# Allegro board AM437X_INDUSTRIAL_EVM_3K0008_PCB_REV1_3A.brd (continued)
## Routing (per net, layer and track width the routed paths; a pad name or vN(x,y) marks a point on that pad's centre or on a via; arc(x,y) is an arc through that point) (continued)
DDR_A6: length 94.3
  TOP w0.102: v1(81.34,60.82) 81.51,60.82 81.78,61.11 U11.R4 ; U20.R8 76.46,29.62 v1(76.46,29.62) 77.05,29.62 77.25,29.82 77.49,29.82 77.49,29.82 78.12,29.82 80.84,32.54 80.84,33.94 81.36,34.46 81.36,46.05 81.24,46.17 79.67,46.17 79.55,46.29 79.55,46.46 79.67,46.58 81.24,46.58 81.36,46.7 81.36,46.87 81.24,46.98 79.67,46.98 79.55,47.1 79.55,47.27 79.67,47.39 81.24,47.39 81.36,47.51 81.36,47.9 81.24,48.01 80.56,48.01 80.44,48.13 80.44,48.3 80.56,48.42 81.24,48.42 81.36,48.54 81.36,48.99 v1(81.18,49.17) ; U21.R8 v1(95.13,29.62)
  L3_SIG1 w0.102: v1(95.13,29.62) 94.75,30 93.2,30 92.79,29.59 92.21,29.59 92.18,29.62 91.84,29.62 90.45,28.23 90.45,26.15 90.27,25.97 88.51,25.97 87.03,27.46 86.01,27.46 85.89,27.34 85.89,26.96 85.77,26.84 85.6,26.84 85.48,26.96 85.48,27.34 85.36,27.46 85.2,27.46 85.08,27.34 85.08,26.96 84.96,26.84 84.79,26.84 84.67,26.96 84.67,27.34 84.55,27.46 84.38,27.46 84.26,27.34 84.26,26.96 84.14,26.84 83.98,26.84 83.86,26.96 83.86,27.34 83.74,27.46 83.57,27.46 83.45,27.34 83.45,26.96 83.33,26.84 83.16,26.84 83.04,26.96 83.04,27.34 82.93,27.46 82.76,27.46 82.64,27.34 82.64,27.06 82.52,26.94 82.35,26.94 82.23,27.06 82.23,27.34 82.11,27.46 81.94,27.46 81.83,27.34 81.83,27.06 81.71,26.94 81.54,26.94 81.42,27.06 81.42,27.34 81.3,27.46 81.13,27.46 81.01,27.34 81.01,27.06 80.89,26.94 80.73,26.94 80.61,27.06 80.61,27.34 80.49,27.46 80.32,27.46 80.2,27.34 80.2,27.06 80.08,26.94 79.91,26.94 79.79,27.06 79.79,27.34 79.67,27.46 78.62,27.46 78.5,27.58 78.5,27.69 78.38,27.81 78.22,27.81 78.1,27.69 78.1,27.58 77.98,27.46 77.42,27.46 77.05,27.83 77.05,28.8 76.46,29.38 v1(76.46,29.62)
  L4_SIG2 w0.102: v1(81.34,60.82) 81.34,60.21 80.97,59.84 80.97,59.25 80.85,59.13 80.37,59.13 80.25,59.01 80.25,58.84 80.37,58.72 80.85,58.72 80.97,58.6 80.97,57.21 81.31,56.87 81.31,56.4 81.08,56.16 81.08,55.97 80.96,55.85 79.91,55.85 79.79,55.73 79.79,55.56 79.91,55.45 80.96,55.45 81.08,55.33 81.08,55.16 80.96,55.04 79.91,55.04 79.79,54.92 79.79,54.75 79.91,54.63 80.96,54.63 81.08,54.51 81.08,53.82 81.31,53.59 81.89,53.59 82.06,53.42 82.06,51.9 81.94,51.78 81.86,51.78 81.74,51.66 81.74,51.49 81.86,51.37 81.94,51.37 82.06,51.25 82.06,51.09 81.94,50.97 80.92,50.97 80.8,50.85 80.8,50.68 80.92,50.56 81.94,50.56 82.06,50.44 82.06,50.08 81.94,49.96 81.79,49.96 81.67,49.84 81.67,49.68 81.79,49.56 81.94,49.56 82.06,49.44 82.06,49.27 81.94,49.15 81.79,49.15 81.67,49.03 81.67,48.86 81.79,48.74 81.94,48.74 82.06,48.62 82.06,48.39 81.68,48.01 81.1,48.01 80.9,48.21 80.9,48.89 v1(81.18,49.17)
  BOTTOM w0.102: v1(95.13,29.62) 96.11,29.62 96.64,29.08 R516.2
DDR_A7: length 89.3
  TOP w0.102: U21.R2 89.93,29.23 v1(89.56,29.61) ; v1(80.92,60.43) 80.95,60.4 81.54,60.4 U11.R3 ; v1(71.66,29.57) 71.31,29.22 U20.R2 71.65,28.83 72.64,28.83 72.97,28.51 72.97,27.96 72.68,27.67 72.68,26.93 74.09,25.52 79.75,25.52 85.65,31.42 85.65,34.97 85.27,35.36 85.27,43.31 v1(85.44,43.48)
  L4_SIG2 w0.102: v1(85.44,43.48) 83.08,43.48 82.96,43.6 82.96,43.95 82.83,44.08 82.66,44.08 82.55,43.97 82.55,43.6 82.43,43.48 82.26,43.48 82.14,43.6 82.14,44.09 82.02,44.21 81.86,44.21 81.74,44.09 81.74,43.6 81.62,43.48 81.3,43.48 81,43.78 81,46.17 80.34,46.83 80.34,51.94 79.24,53.05 79.24,56.37 80.24,57.37 80.24,57.71 79.95,58.01 79.95,59.46 v1(80.92,60.43) ; v1(89.56,29.61) 89.03,29.08 89.03,27.67 88.7,27.34 88,27.34 87.61,27.73 87.44,27.73 87.2,27.49 87.03,27.49 86.91,27.61 86.91,27.78 87.15,28.02 87.15,28.19 87.03,28.31 86.86,28.31 86.62,28.07 86.45,28.07 86.33,28.19 86.33,28.36 86.58,28.6 86.58,28.77 86.46,28.88 86.29,28.88 86.05,28.64 85.88,28.64 85.76,28.76 85.76,28.93 86,29.17 86,29.34 85.8,29.54 78.66,29.54 78.05,28.92 77.19,28.92 76.87,29.24 76.87,29.84 76.41,30.3 76.41,30.56 76.08,30.89 75.59,30.89 75.25,30.55 75.25,30.25 74.99,29.99 74.54,29.99 74.12,29.57 72.97,29.57 72.87,29.66 72.4,29.66 72.3,29.57 v1(71.66,29.57)
  BOTTOM w0.102: R534.2 87.76,27.38 88.12,27.75 88.12,28.38 88.45,28.7 88.6,28.7 89.5,29.61 v1(89.56,29.61)
DDR_A8: length 97.2
  TOP w0.102: U20.T8 76.06,28.5 v1(76.39,28.83) 77.24,28.83 77.28,28.87 77.79,28.87 78.79,29.87 78.81,29.87 79.58,30.65 79.58,30.67 81.27,32.36 81.27,33.8 81.77,34.3 81.77,47.46 v1(82.21,47.9) ; v1(81.79,57.73) 82.19,58.14 82.19,58.98 82.09,59.08 82.09,59.48 81.78,59.78 U11.R2 ; v1(95.17,28.78) U21.T8 94.73,28.04 95.76,27.01 R221.2
  L3_SIG1 w0.102: v1(95.17,28.78) 94.35,28.78 93.52,29.62 93.12,29.62 92.88,29.39 92.88,29.31 91.47,27.89 91.47,25.85 91.17,25.56 88.03,25.56 87.91,25.68 87.91,25.99 87.8,26.11 87.63,26.11 87.51,25.99 87.51,25.68 87.39,25.56 87.22,25.56 87.1,25.68 87.1,26.17 86.98,26.29 86.84,26.29 86.7,26.15 86.7,25.68 86.58,25.56 86.41,25.56 86.29,25.68 86.29,26.3 86.17,26.42 86,26.42 85.88,26.3 85.88,25.68 85.76,25.56 85.6,25.56 85.48,25.68 85.48,26.3 85.36,26.42 85.19,26.42 85.07,26.3 85.07,25.68 84.95,25.56 84.78,25.56 84.66,25.68 84.66,26.3 84.54,26.42 84.38,26.42 84.26,26.3 84.26,25.68 84.14,25.56 83.87,25.56 82.91,26.52 76.61,26.52 76.39,26.73 v1(76.39,28.83) ; v1(82.21,47.9) 84.57,47.9 84.82,48.15 84.82,48.32 84.63,48.5 84.63,48.67 84.75,48.79 84.92,48.79 85.87,47.83 86.06,47.83 86.18,47.95 86.18,48.1 85.2,49.08 85.2,49.25 85.32,49.37 85.49,49.37 85.68,49.18 85.85,49.18 85.98,49.31 85.98,50.93 85.86,51.05 82.46,51.05 82.34,51.17 82.34,51.34 82.46,51.46 85.86,51.46 85.98,51.58 85.98,52.48 85.79,52.67 85.62,52.67 84.74,51.79 84.58,51.79 84.46,51.91 84.46,52.08 85.34,52.96 85.34,53.13 85.22,53.25 85.05,53.25 83.85,52.04 83.67,52.04 83.55,52.16 83.55,52.32 84.76,53.53 84.76,53.7 84.64,53.82 84.47,53.82 83.59,52.94 83.43,52.94 83.31,53.06 83.31,53.23 84.19,54.11 84.19,54.28 84.01,54.45 83.85,54.45 83.35,53.95 83.18,53.95 83.06,54.07 83.06,54.24 83.56,54.74 83.56,54.91 82.67,55.8 82.67,56.85 v1(81.79,57.73)
DDR_A9: length 94.4
  TOP w0.102: U20.R3 72.53,29.22 v1(72.57,29.26) 72.64,29.26 73.19,28.7 73.19,27.83 73.11,27.75 73.11,27.11 74.27,25.95 79.44,25.95 85.21,31.72 85.21,34.84 84.73,35.32 84.73,44.21 v1(85.52,45) ; v1(81.78,58.39) U11.R1 ; R217.2 91.19,27.43 92.01,28.25 92.01,29.18 v1(91.99,29.19) 91.97,29.22 U21.R3
  L3_SIG1 w0.102: v1(81.78,58.39) 81.78,58.81 82.09,59.11 82.76,59.11 83.77,58.11 83.77,56.77 84.46,56.08 84.97,56.08 85.13,55.92 85.71,55.92 85.83,55.8 85.83,55.64 85.45,55.26 85.45,55.09 85.57,54.97 85.74,54.97 86.3,55.53 86.46,55.53 86.58,55.41 86.58,55.24 86.03,54.68 86.03,54.51 86.14,54.4 86.31,54.4 86.87,54.95 87.04,54.95 87.16,54.83 87.16,54.67 86.6,54.11 86.6,53.94 86.72,53.82 86.89,53.82 87.45,54.38 87.61,54.38 87.73,54.26 87.73,54.09 87.18,53.53 87.18,53.36 87.53,53.01 87.53,52.75 87.65,52.63 88.52,52.63 88.64,52.52 88.64,52.35 88.52,52.23 87.65,52.23 87.53,52.11 87.53,51.94 87.65,51.82 88.54,51.82 88.66,51.7 88.66,51.53 88.54,51.42 87.65,51.42 87.53,51.3 87.53,45.64 87.01,45.12 85.65,45.12 v1(85.52,45)
  L4_SIG2 w0.102: v1(72.57,29.26) 73.59,28.23 73.59,27.13 73.88,26.83 78.19,26.83 78.71,27.36 83.62,27.36 83.73,27.24 83.73,26.96 83.85,26.84 84.02,26.84 84.14,26.96 84.14,27.24 84.26,27.36 84.43,27.36 84.55,27.24 84.55,26.96 84.67,26.84 84.83,26.84 84.95,26.96 84.95,27.24 85.07,27.36 85.29,27.36 85.98,26.67 86.61,26.03 90.26,26.03 90.68,26.46 90.68,28.5 91.19,29.01 91.81,29.01 v1(91.99,29.19)
DDR_A10: length 95.5
  TOP w0.102: v1(80.94,62.1) 80.75,62.29 80.14,62.29 U11.M6 ; v1(74.79,33.01) 74.79,32.89 U20.L7 ; R205.2 99.31,31.24 99.16,31.39 97.76,31.39 96.77,32.38 96.39,32.38 96.01,32 94.34,32 U21.L7 v1(93.38,32.51)
  L3_SIG1 w0.102: v1(93.38,32.51) 93.05,32.18 92.33,32.18 92.18,32.03 91.61,32.03 90.71,32.92 90.71,33.05 90.36,33.41 87.2,33.41 86.76,33.85 86.76,34.67 86.23,35.2 85.8,35.2 85.68,35.09 85.68,34.61 85.56,34.49 85.1,34.49 84.98,34.61 84.98,35.19 84.86,35.31 84.69,35.31 84.57,35.19 84.57,34.61 84.46,34.49 84.29,34.49 84.17,34.61 84.17,35.19 84.05,35.31 83.88,35.31 83.76,35.19 83.76,34.61 83.64,34.49 83.47,34.49 83.36,34.61 83.36,35.19 83.24,35.31 83.07,35.31 82.95,35.19 82.95,34.61 82.83,34.49 82.66,34.49 82.54,34.61 82.54,35.19 82.42,35.31 82.26,35.31 82.14,35.19 82.14,34.61 82.02,34.49 81.85,34.49 81.73,34.61 81.73,35.19 81.61,35.31 81.44,35.31 81.32,35.19 81.32,34.61 81.2,34.49 81.04,34.49 80.92,34.61 80.92,35.19 80.8,35.31 80.63,35.31 80.51,35.19 80.51,34.61 80.39,34.49 80.26,34.49 80.02,34.25 76.87,34.25 76.45,34.67 74.42,34.67 74.04,34.29 74.04,33.75 v1(74.79,33.01)
  L4_SIG2 w0.102: v1(80.94,62.1) 80.29,61.45 80.29,60.57 74.51,54.8 74.51,51.43 74.63,51.31 75.45,51.31 75.57,51.19 75.57,51.03 75.45,50.91 74.63,50.91 74.51,50.79 74.51,50.62 74.63,50.5 75.45,50.5 75.57,50.38 75.57,50.21 75.45,50.09 74.63,50.09 74.51,49.97 74.51,49.81 74.63,49.69 75.45,49.69 75.57,49.57 75.57,49.4 75.45,49.28 74.63,49.28 74.51,49.16 74.51,48.99 74.63,48.87 75.45,48.87 75.57,48.75 75.57,48.59 75.45,48.47 74.63,48.47 73.74,47.57 70.49,47.57 69.03,46.11 69.03,44.06 67.69,42.72 67.69,41.71 68.02,41.38 68.02,39.32 67.56,38.86 67.56,38.32 67.91,37.97 67.91,32.71 68.39,32.23 69.67,32.23 70.71,33.27 71.63,33.27 72.44,32.46 74.24,32.46 v1(74.79,33.01)
DDR_A11: length 95.1
  TOP w0.102: U11.T5 82.43,62.19 82.74,62.49 83.01,62.49 83.04,62.53 v1(83.26,62.53) ; U20.R7 74.78,28.74 v1(74.78,28.17) 75.18,27.78 77.92,27.78 82.14,32 82.14,33.52 82.58,33.96 82.58,46.89 82.87,47.17 83.03,47.17 83.17,47.03 83.34,47.03 83.46,47.15 83.46,47.32 83.32,47.46 83.32,47.63 83.44,47.75 83.61,47.75 83.8,47.56 83.95,47.56 84.07,47.68 84.07,47.86 83.95,47.98 83.95,48.15 84.65,48.85 84.65,49.01 84.58,49.07 v1(84.3,49.07) ; U21.R7 v1(93.29,29.22) 92.68,28.61 92.68,27.81 93.12,27.38 93.12,24.74 R219.2
  L3_SIG1 w0.102: v1(74.78,28.17) 74.78,25.67 75.31,25.15 75.77,25.15 75.89,25.27 75.89,25.76 76.01,25.88 76.18,25.88 76.3,25.76 76.3,25.27 76.42,25.15 76.58,25.15 76.7,25.27 76.7,25.76 76.82,25.88 76.99,25.88 77.11,25.76 77.11,25.27 77.23,25.15 77.4,25.15 77.52,25.27 77.52,25.76 77.63,25.88 77.8,25.88 77.92,25.76 77.92,25.27 78.04,25.15 78.21,25.15 78.33,25.27 78.33,25.76 78.45,25.88 78.62,25.88 78.73,25.76 78.73,25.27 78.85,25.15 79.02,25.15 79.14,25.27 79.14,25.76 79.26,25.88 79.43,25.88 79.55,25.76 79.55,25.27 79.67,25.15 79.83,25.15 79.95,25.27 79.95,25.76 80.07,25.88 80.24,25.88 80.36,25.76 80.36,25.27 80.48,25.15 91.45,25.15 91.82,25.52 91.82,27.69 93.29,29.15 v1(93.29,29.22)
  L4_SIG2 w0.102: v1(83.26,62.53) 82.99,62.53 82.96,62.49 82.58,62.49 81.95,61.86 81.95,59.22 82.19,58.98 82.19,58.18 82.34,58.03 82.51,58.03 82.67,58.19 82.84,58.19 82.96,58.07 82.96,57.9 82.8,57.74 82.8,57.57 82.92,57.45 82.92,57.28 82.8,57.16 82.45,57.16 82.33,57.04 82.33,56.87 82.45,56.75 82.8,56.75 82.92,56.63 82.92,54.34 83.04,54.22 83.71,54.22 83.83,54.1 83.83,53.93 83.71,53.81 83.04,53.81 82.92,53.69 82.92,53.53 83.04,53.41 84.34,53.41 84.47,53.28 84.47,53.11 84.36,53 83.04,53 82.92,52.88 82.92,52.71 83.04,52.59 84.23,52.59 84.35,52.48 84.35,52.31 84.23,52.19 83.04,52.19 82.92,52.07 82.92,51.9 83.04,51.78 83.94,51.78 84.06,51.66 84.06,51.49 83.94,51.38 83.04,51.38 82.92,51.26 82.92,51.01 83.02,50.91 83.77,50.91 83.95,50.73 83.95,49.41 v1(84.3,49.07)
DDR_A12: length 95.5
  TOP w0.102: v1(85.17,47.8) 85.17,47.45 84.91,47.19 84.14,47.19 83.74,46.78 83.74,46.11 83.44,45.81 83.44,33.67 82.99,33.21 82.99,31.24 78.95,27.2 74.79,27.2 74.64,27.34 74.46,27.34 73.9,27.9 73.9,29.78 74.51,30.39 v1(74.82,30.39) 75.24,30.82 U20.N7 ; v1(82.92,62.09) 82.92,61.96 82.43,61.48 U11.T4 ; U21.N7 v1(93.34,30.82)
  L3_SIG1 w0.102: v1(93.34,30.82) 92.94,31.22 91.84,31.22 91.83,31.21 91.2,31.21 90.41,32 86.92,32 86.29,31.37 85.89,31.37 85.77,31.49 85.77,32.73 85.66,32.85 85.49,32.85 85.37,32.73 85.37,31.49 85.25,31.37 84.53,31.37 83.31,32.59 82.67,32.59 82.55,32.47 82.55,31.47 82.43,31.35 82.26,31.35 82.14,31.47 82.14,32.47 82.03,32.59 81.86,32.59 81.74,32.47 81.74,31.47 81.62,31.35 81.45,31.35 81.33,31.47 81.33,32.47 81.21,32.59 81.04,32.59 80.93,32.47 80.93,31.47 80.81,31.35 80.64,31.35 80.52,31.47 80.52,32.47 80.4,32.59 80.11,32.59 79.98,32.46 79.98,31.72 78.74,30.48 77.93,30.48 77.49,30.91 76.6,30.91 76.45,31.06 75.48,31.06 74.82,30.41 v1(74.82,30.39)
  L4_SIG2 w0.102: v1(82.92,62.09) 82.17,61.34 82.17,59.81 83.33,58.66 83.33,55.18 85.98,52.53 85.98,52.34 85.89,52.25 85.18,52.25 85.07,52.14 85.07,51.97 85.2,51.84 86.04,51.84 86.16,51.72 86.16,51.56 86.04,51.44 85.02,51.44 84.9,51.31 84.9,51.15 85.02,51.03 86.04,51.03 86.16,50.91 86.16,50.59 86.04,50.47 85.46,50.47 85.34,50.35 85.34,50.18 85.46,50.06 86.04,50.06 86.16,49.94 86.16,49.77 86.04,49.66 85.12,49.66 84.98,49.51 84.98,49.16 85.13,49.01 86.03,49.01 86.15,48.89 86.15,48.72 86.03,48.6 85.46,48.6 85.34,48.48 85.34,47.98 v1(85.17,47.8)
  BOTTOM w0.102: R527.2 95.76,26.16 95.25,26.67 95.11,26.67 94.74,27.04 94.74,27.72 93.75,28.71 93.75,30.41 v1(93.34,30.82)
DDR_A13: length 89.1
  TOP w0.102: U21.T3 v1(91.29,28.42) 91.29,27.83 90.98,27.52 90.98,26.09 90.04,25.15 R216.2 ; v1(72.56,28.23) 72.38,28.42 U20.T3 72.06,27.81 72.24,27.63 72.24,26.75 73.91,25.08 79.92,25.08 86.01,31.17 86.01,35.25 85.67,35.59 85.67,42.69 v1(85.98,43) ; v1(81.35,61.68) 81.13,61.68 81.12,61.69 80.79,61.69 U11.N5
  L4_SIG2 w0.102: v1(91.29,28.42) 91.29,26.52 90.43,25.65 86.61,25.65 85.84,26.43 82.69,26.43 82.5,26.62 81.81,26.62 81.5,26.31 81.5,26.03 81.38,25.91 81.21,25.91 81.09,26.03 81.09,26.31 80.97,26.43 80.8,26.43 80.68,26.31 80.68,26.03 80.56,25.91 80.4,25.91 80.28,26.03 80.28,26.31 80.16,26.43 79.99,26.43 79.87,26.31 79.87,26.03 79.75,25.91 79.58,25.91 79.46,26.03 79.46,26.31 79.34,26.43 79.18,26.43 79.06,26.31 79.06,26.03 78.94,25.91 78.77,25.91 78.65,26.03 78.65,26.31 78.53,26.43 73.26,26.43 72.56,27.13 v1(72.56,28.23) ; v1(85.98,43) 85.98,43.46 86.42,43.9 86.42,46.09 85.88,46.63 85.34,46.63 84.77,47.21 84.56,47.21 84.44,47.33 84.44,47.96 84.32,48.08 84.16,48.08 84.04,47.96 84.04,47.33 83.92,47.21 83.75,47.21 83.63,47.33 83.63,47.96 83.51,48.08 83.34,48.08 83.22,47.96 83.22,47.33 83.1,47.21 82.85,47.21 82.68,47.39 82.68,48.04 82.51,48.2 82.51,56.17 81.17,57.51 81.17,59.09 81.74,59.66 81.74,61.29 v1(81.35,61.68)
DDR_A14: length 94.9
  TOP w0.102: v1(83.31,48.53) 83.01,48.24 83.01,47.94 82.18,47.1 82.18,34.13 81.71,33.66 81.71,32.14 78.06,28.49 78.06,28.41 77.67,28.01 75.67,28.01 U20.T7 75.26,28.43 75.63,28.8 v1(75.66,28.8) ; v1(81.19,49.94) 80.64,49.94 80.46,50.13 80.46,50.8 80.58,50.92 81.81,50.92 81.93,50.8 81.93,48.86 82.06,48.73 82.23,48.73 82.34,48.83 82.34,50.8 82.46,50.92 84.53,50.92 84.65,51.04 84.65,51.2 84.52,51.33 81.86,51.33 81.73,51.46 81.73,51.63 81.84,51.73 83.73,51.73 83.85,51.84 83.85,52.01 83.72,52.14 81.92,52.14 81.8,52.26 81.8,52.43 81.91,52.55 83.13,52.55 83.25,52.66 83.25,52.83 83.13,52.95 82.25,52.95 82.13,53.07 82.13,53.6 81.96,53.77 81.37,53.77 81.08,54.06 81.08,55.65 82,56.57 82,57.34 83,58.34 83,58.87 82.78,59.1 82.78,59.44 82.56,59.66 82.34,59.66 82.13,59.87 82.13,60.34 U11.T3 ; U21.T7 v1(93.14,28.4) 94.61,26.92 R220.2
  L3_SIG1 w0.102: v1(93.14,28.4) 93.14,26.21 91.67,24.74 75.03,24.74 74.04,25.73 74.04,26.61 73.92,26.73 73.37,26.73 73.25,26.85 73.25,27.02 73.37,27.14 73.92,27.14 74.04,27.26 74.04,27.43 73.92,27.55 72.99,27.55 72.87,27.67 72.87,27.83 72.99,27.95 73.92,27.95 74.04,28.07 74.04,28.45 74.39,28.8 v1(75.66,28.8)
  BOTTOM w0.102: v1(81.19,49.94) 82.6,48.53 v1(83.31,48.53)
DDR_BA0: length 97.8
  TOP w0.102: U21.M2 89.58,31.27 v1(89.56,31.27) ; U20.M2 v1(71.66,32.02) ; v1(77.9,48.66) 77.9,49.36 77.8,49.46 77.8,51.48 77.92,51.59 78.58,51.59 78.7,51.71 78.7,51.88 78.58,52 77.92,52 77.8,52.12 77.8,52.29 77.92,52.41 78.58,52.41 78.7,52.53 78.7,52.69 78.58,52.81 77.92,52.81 77.8,52.93 77.8,53.56 78.49,54.26 78.49,56.39 78.33,56.55 78.33,57.2 78.84,57.71 78.84,58.13 78.54,58.44 U11.K1
  L4_SIG2 w0.102: v1(71.66,32.02) 75.16,32.02 75.66,32.52 78.27,32.52 78.3,32.49 80.03,32.49 81.08,33.53 81.47,33.53 81.59,33.41 81.59,32.33 81.71,32.21 81.88,32.21 82,32.33 82,33.56 82.12,33.68 82.29,33.68 82.41,33.56 82.41,32.33 82.53,32.21 82.69,32.21 82.81,32.33 82.81,33.43 82.93,33.55 83.1,33.55 83.22,33.43 83.22,32.33 83.34,32.21 83.51,32.21 83.63,32.33 83.63,33.41 83.74,33.53 85.66,33.53 85.78,33.41 85.78,32.17 85.9,32.05 86.07,32.05 86.19,32.17 86.19,33.41 86.31,33.53 86.51,33.53 86.69,33.35 86.69,32.43 86.82,32.3 87.18,32.3 87.3,32.18 87.3,31.16 87.42,31.04 87.59,31.04 87.71,31.16 87.71,31.85 87.92,32.06 88.73,32.06 89.53,31.27 v1(89.56,31.27) ; v1(77.9,48.66) 77.73,48.66 77.52,48.45 77.52,47.86 77.93,47.46 79.51,47.46 79.8,47.75 v1(79.8,49.03)
  BOTTOM w0.102: v1(89.56,31.27) 89.56,31.25 88.96,30.65 88.96,30.54 88.42,30 88.34,30 88,29.65 88,29.08 85.72,26.8 R522.2 ; v1(79.8,49.03) 80.45,48.38 80.62,48.38 80.84,48.6 81.01,48.6 81.13,48.48 81.13,48.31 80.91,48.09 80.91,47.92 81.87,46.95 81.87,46.33 82.91,45.3 82.91,44.86 83.21,44.56 83.21,40.83 82.06,39.68 82.06,39.4 82.18,39.28 83.1,39.28 83.22,39.16 83.22,38.99 83.1,38.87 82.18,38.87 82.06,38.75 82.06,38.59 82.18,38.47 83.1,38.47 83.22,38.35 83.22,38.18 83.1,38.06 82.18,38.06 82.06,37.94 82.06,37.77 82.18,37.65 83.1,37.65 83.22,37.53 83.22,37.37 83.1,37.25 82.18,37.25 82.06,37.13 82.06,36.96 82.18,36.84 83.1,36.84 83.22,36.72 83.22,36.55 83.1,36.43 82.18,36.43 82.06,36.31 82.06,36.15 82.18,36.03 83.1,36.03 83.22,35.91 83.22,35.74 83.1,35.62 82.18,35.62 82.06,35.5 82.06,34.38 81.64,33.95 81.64,33.93 80.33,32.63 78.36,32.63 78.2,32.79 75.72,32.79 75.39,32.46 73.11,32.46 72.66,32.02 v1(71.66,32.02)
DDR_BA1: length 101.1
  TOP w0.102: U21.N8 v1(95.13,31.22) 95.2,31.29 96.85,31.29 97.54,30.61 97.54,29.02 97.72,28.83 100.9,28.83 101.22,29.15 R206.2 ; U11.K2 78.23,59.69 78.23,58.17 v1(78.44,57.96) ; v1(75.65,30.38) 75.66,30.38 76.06,30.78 U20.N8 76.06,30.85 76.5,31.29 77.53,31.29 77.77,31.52 77.77,31.67 78.47,32.38 78.54,32.45 78.83,32.45 78.97,32.31 79.14,32.31 79.26,32.43 79.26,32.59 79.11,32.74 79.11,32.91 79.23,33.03 79.4,33.03 79.55,32.88 79.74,32.88 79.86,33 79.86,33.14 79.69,33.32 79.69,33.48 79.95,33.75 79.95,34.22 80.42,34.68 80.42,43.47 79.52,44.37 79.52,44.94 79.27,45.19 v1(78.44,45.19)
  L3_SIG1 w0.102: v1(75.65,30.38) 76.56,30.38 77.12,29.82 77.88,29.82 78.1,29.59 78.79,29.59 78.91,29.47 78.91,29.22 79.03,29.1 79.2,29.1 79.32,29.22 79.32,29.47 79.44,29.59 79.61,29.59 79.73,29.47 79.73,29.22 79.85,29.1 80.01,29.1 80.13,29.22 80.13,29.47 80.25,29.59 80.42,29.59 80.54,29.47 80.54,29.22 80.66,29.1 80.83,29.1 80.95,29.22 80.95,29.47 81.06,29.59 81.23,29.59 81.35,29.47 81.35,29.22 81.47,29.1 81.64,29.1 81.76,29.22 81.76,29.47 81.88,29.59 82.05,29.59 82.16,29.47 82.16,29.22 82.28,29.1 82.45,29.1 82.57,29.22 82.57,29.47 82.69,29.59 82.86,29.59 82.98,29.47 82.98,29.22 83.1,29.1 83.26,29.1 83.38,29.22 83.38,29.47 83.5,29.59 83.67,29.59 83.79,29.47 83.79,29.22 83.91,29.1 84.08,29.1 84.2,29.22 84.2,29.47 84.32,29.59 84.48,29.59 84.6,29.47 84.6,29.22 84.72,29.1 84.89,29.1 85.01,29.22 85.01,29.47 85.13,29.59 85.3,29.59 85.42,29.47 85.42,29.22 85.54,29.1 85.7,29.1 85.82,29.22 85.82,29.47 85.94,29.59 86.11,29.59 86.23,29.47 86.23,29.22 86.35,29.1 86.52,29.1 86.64,29.22 86.64,29.47 86.75,29.59 87.12,29.59 87.55,30.02 88.32,30.02 89.15,30.86 90.55,30.86 90.8,30.61 90.8,29.79 91.03,29.57 91.48,29.57 92.53,30.61 92.84,30.61 93.03,30.41 94.93,30.41 95.13,30.61 v1(95.13,31.22) ; v1(78.44,57.96) 78.44,53.89 75.89,51.35 75.73,51.35 75.18,51.91 75,51.91 74.88,51.79 74.88,51.62 75.44,51.07 75.44,50.9 75.21,50.67 75.21,49.57 75.09,49.45 73.1,49.45 72.98,49.34 72.98,49.17 73.1,49.05 75.09,49.05 75.21,48.93 75.21,48.76 75.09,48.64 73.1,48.64 72.98,48.52 72.98,48.35 73.1,48.24 75.09,48.24 75.21,48.12 75.21,47.93 75.09,47.81 73.34,47.81 73.22,47.69 73.22,47.53 73.34,47.41 75.09,47.41 75.21,47.29 75.21,47.12 75.09,47 73.72,47 73.6,46.88 73.6,46.52 73.79,46.33 73.79,46.16 73.36,45.73 73.36,45.56 73.48,45.44 73.65,45.44 74.08,45.87 74.25,45.87 75.51,44.61 75.51,43.4 75.63,43.28 75.85,43.28 75.97,43.4 75.97,44.37 76.09,44.49 76.25,44.49 76.37,44.37 76.37,43.78 76.49,43.66 76.66,43.66 76.78,43.78 76.78,44.83 76.9,44.95 77.24,44.95 77.48,45.19 v1(78.44,45.19)
DDR_BA2: length 93.8
  TOP w0.102: v1(78.97,60.43) 78.96,60.43 U11.K3 ; U20.M3 71.7,31.25 v1(71.61,31.25) ; U21.M3 v1(91.37,31.62)
  L3_SIG1 w0.102: v1(91.37,31.62) 90.6,32.38 86.87,32.38 86.31,32.94 86.31,33.78 86.06,34.04 85.46,34.04 85.34,33.92 85.34,33.32 85.23,33.2 85.06,33.2 84.94,33.32 84.94,33.92 84.82,34.04 84.65,34.04 84.53,33.92 84.53,33.32 84.41,33.2 84.24,33.2 84.13,33.32 84.13,33.92 84.01,34.04 83.84,34.04 83.72,33.92 83.72,33.32 83.6,33.2 83.43,33.2 83.31,33.32 83.31,33.92 83.19,34.04 83.03,34.04 82.91,33.92 82.91,33.32 82.79,33.2 82.62,33.2 82.5,33.32 82.5,33.92 82.38,34.04 82.21,34.04 82.09,33.92 82.09,33.32 81.97,33.2 81.81,33.2 81.69,33.32 81.69,33.92 81.57,34.04 81.4,34.04 81.28,33.92 81.28,33.32 81.16,33.2 80.99,33.2 80.87,33.32 80.87,33.92 80.76,34.04 80.48,34.04 79.3,32.85 79.3,31.61 78.57,30.89 78.46,30.89 78.28,30.71 77.98,30.71 77.92,30.78 77.41,31.29 76.54,31.29 75.93,31.89 73.13,31.89 72.49,31.25 v1(71.61,31.25) ; v1(65.95,45.18) 65.74,45.39 65.34,45.39 65.16,45.39 64.94,45.6 64.94,46.29 65.6,46.95 65.77,46.95 65.89,46.83 65.89,45.82 66.01,45.7 66.18,45.7 66.3,45.82 66.3,46.83 66.42,46.95 67.45,46.95 67.65,47.14 67.65,47.45 68.29,48.09 68.46,48.09 68.8,47.75 68.97,47.75 69.09,47.87 69.09,48.04 68.75,48.38 68.75,48.55 68.87,48.67 69.03,48.67 69.31,48.39 69.48,48.39 69.6,48.51 69.6,48.68 69.32,48.96 69.32,49.13 69.44,49.24 69.61,49.24 69.89,48.97 70.06,48.97 70.17,49.08 70.17,49.25 69.9,49.53 69.9,49.7 70.01,49.82 70.18,49.82 70.46,49.54 70.63,49.54 70.75,49.66 70.75,49.83 70.47,50.11 70.47,50.28 70.59,50.39 70.76,50.39 71.04,50.12 71.2,50.12 71.32,50.23 71.32,50.4 71.04,50.68 71.04,50.85 71.16,50.97 71.33,50.97 71.61,50.69 71.78,50.69 71.9,50.81 71.9,50.98 71.62,51.26 71.62,51.43 76.93,56.74 76.93,58.4 v1(78.97,60.43)
  L4_SIG2 w0.102: v1(65.95,45.18) 65.8,45.34 65.05,45.34 64.35,44.64 64.35,44.05 65.38,43.02 65.55,43.02 66.16,43.63 66.33,43.63 66.44,43.51 66.44,43.34 65.84,42.73 65.84,42.57 66.17,42.23 66.17,40.3 66.85,39.62 66.85,35.05 67.7,34.2 67.7,32.63 67.78,32.55 67.78,32.04 68.07,31.75 69.24,31.75 69.66,31.34 69.99,31.34 70.15,31.5 71.37,31.5 v1(71.61,31.25)
  BOTTOM w0.102: v1(91.37,31.62) 91.37,30.64 90.96,30.23 90.96,29.87 90.87,29.78 90.87,27.5 91.19,27.18 R531.2
DDR_CASN: length 98.7
  TOP w0.102: v1(79.88,51.78) 79.88,53.22 79.81,53.29 79.81,56.79 80.24,57.22 80.24,57.71 80.11,57.84 80.11,59.16 80.18,59.22 80.18,60.34 U11.N3 ; U21.K3 v1(91.19,33.02) ; v1(72.44,33.6) 72.44,33.6 U20.K3
  L3_SIG1 w0.102: v1(91.19,33.02) 90.47,33.74 88.41,33.74 87.93,34.21 87.93,34.38 88.03,34.48 88.03,34.65 87.91,34.77 87.74,34.77 87.64,34.67 87.47,34.67 87.35,34.79 87.35,34.96 87.46,35.06 87.46,35.23 87.34,35.35 87.17,35.35 87.07,35.24 86.9,35.24 85.84,36.3 85.5,36.3 85.38,36.18 85.38,35.81 85.26,35.69 85.09,35.69 84.97,35.81 84.97,36.18 84.85,36.3 84.69,36.3 84.57,36.18 84.57,35.81 84.45,35.69 84.28,35.69 84.16,35.81 84.16,36.18 84.04,36.3 83.87,36.3 83.75,36.18 83.75,35.81 83.64,35.69 83.47,35.69 83.35,35.81 83.35,36.18 83.23,36.3 83.06,36.3 82.94,36.18 82.94,35.81 82.82,35.69 82.65,35.69 82.54,35.81 82.54,36.18 82.42,36.3 82.25,36.3 82.13,36.18 82.13,35.81 82.01,35.69 81.84,35.69 81.72,35.81 81.72,36.18 81.6,36.3 81.44,36.3 81.32,36.18 81.32,35.81 81.2,35.69 81.03,35.69 80.91,35.81 80.91,36.18 80.79,36.3 80.59,36.3 80.47,36.18 80.47,35.73 80.35,35.61 80.18,35.61 80.06,35.73 80.06,36.2 79.94,36.32 79.5,36.32 79.4,36.22 79.4,35.66 79.15,35.41 77.46,35.41 76.68,36.2 74.68,36.2 74.17,36.7 73.41,36.7 73,36.3 73,35.73 72.82,35.55 72.82,34.64 73.01,34.45 73.01,34.17 v1(72.44,33.6)
  L4_SIG2 w0.102: v1(79.88,51.78) 78.33,51.78 77.75,51.21 77.75,49.51 78.2,49.06 78.95,49.06 79.17,49.28 79.17,49.47 v1(79.88,50.18)
  BOTTOM w0.102: v1(72.44,33.6) 72.19,33.35 72.19,32.93 72.5,32.61 72.84,32.61 73.02,32.79 73.69,32.79 74.35,33.45 75.01,33.45 75.36,33.1 80.16,33.1 81.62,34.56 81.62,40.53 82.5,41.4 82.5,41.6 82.38,41.72 81.02,41.72 80.9,41.83 80.9,42 81.02,42.12 82.38,42.12 82.5,42.24 82.5,42.41 82.38,42.53 81.02,42.53 80.9,42.65 80.9,42.82 81.02,42.93 82.38,42.93 82.5,43.05 82.5,43.22 82.38,43.34 81.53,43.34 81.41,43.46 81.41,43.63 81.53,43.75 82.38,43.75 82.5,43.87 82.5,44.03 82.38,44.15 81.3,44.15 81.2,44.26 81.2,44.42 81.33,44.56 82.38,44.56 82.5,44.68 82.5,45.1 82.38,45.21 81.74,45.21 80.7,46.25 80.7,46.41 80.88,46.59 80.88,46.76 80.76,46.88 80.59,46.88 80.41,46.7 80.25,46.7 80.13,46.82 80.13,46.99 80.3,47.16 80.3,47.33 80.18,47.45 80.01,47.45 79.84,47.28 79.67,47.28 79.55,47.4 79.55,47.56 79.73,47.74 79.73,47.91 79.61,48.03 79.44,48.03 79.26,47.85 79.1,47.85 78.87,48.08 78.87,49.16 79.17,49.46 79.17,49.47 v1(79.88,50.18) ; R532.2 90.57,26.31 90.57,29.77 90.75,29.95 90.75,30.31 90.94,30.49 90.94,32.76 v1(91.19,33.02)
DDR_CKE: length 48.8
  TOP w0.102: v1(77.45,33.61) 77.06,33.22 U20.K9 ; U21.K9 v1(96.08,33) 96.14,32.94 97.54,32.94 98.68,31.8 100.76,31.8 R199.2
  L4_SIG2 w0.102: v1(77.9,36.06) 76.96,35.12 76.96,34.1 v1(77.45,33.61) 77.58,33.61 78.06,34.09 78.36,34.09 78.99,34.73 78.99,35.2 80.42,36.63 80.42,37.11 80.64,37.34 85.34,37.34 86.59,36.09 87.02,36.09 87.25,36.32 87.25,37.08 87.88,37.72 89.31,37.72 91.09,35.94 93.04,35.94 93.12,36.02 94.05,36.02 94.71,35.36 94.71,35.02 94.7,35 94.7,33.27 94.97,33 v1(96.08,33)
  BOTTOM w0.102: v1(77.9,36.06) 77.98,36.14 77.98,42.29 77.19,43.08 77.19,43.24 76.79,43.64 76.07,43.64 74.96,44.75 74.96,45.15 74.59,45.52 74.59,45.53 74.17,45.95 R484.1
DDR_CKE0: length 15.5
  TOP w0.102: v1(79.38,60.82) 79.39,60.81 U11.M3
  BOTTOM w0.102: R484.2 74.17,48.98 78.41,53.22 78.41,57.15 78.84,57.58 78.84,58.13 78.78,58.19 78.78,59.33 79.38,59.93 v1(79.38,60.82)
DDR_CLK: length 95.5
  TOP w0.102: v1(93.34,33.86) 93.5,34.02 U21.J7 ; U11.M2 79.54,59.71 79.54,59.03 79.59,58.98 79.59,58.64 79.5,58.56 v1(79.5,58.09) ; v1(74.46,31.37) 74.02,30.93 73.98,30.93 73.96,30.9 73.62,30.9 73.38,31.14 73.38,31.51 73.49,31.62 73.49,33.5 73.84,33.84 74.98,33.84 75.15,34.02 U20.J7 75.6,34.02 75.69,34.11 75.69,34.32 75.81,34.44 77.19,34.44 77.72,33.91 77.97,33.91 78.26,34.21 78.51,34.46 78.51,35.15 79.35,35.99 79.35,36.97 79.23,37.09 78.2,37.09 77.9,37.38 77.9,37.8 78.2,38.09 79.35,38.09 79.46,38.2 79.46,38.37 79.33,38.49 78.2,38.49 77.9,38.79 77.9,39.2 78.2,39.49 79.39,39.49 79.51,39.6 79.51,39.77 79.38,39.9 78.02,39.9 77.72,40.19 77.72,40.6 78.01,40.89 79.41,40.89 79.51,41 79.51,41.17 79.38,41.3 78.01,41.3 77.74,41.57 77.74,41.98 78.06,42.29 79.23,42.29 79.35,42.41 79.35,43.25 78.62,43.98 78.06,43.98 v1(77.85,43.77)
  BOTTOM w0.102: R507.2 99.44,33.78 95.72,33.78 95.53,33.59 93.62,33.59 93.43,33.78 93.42,33.78 v1(93.34,33.86) 93.19,33.71 92.27,33.71 92.18,33.61 91.84,33.61 91.79,33.66 91.54,33.66 91.48,33.72 91.21,33.72 86.71,33.72 86.61,33.83 86.61,34.37 86.31,34.67 85.69,34.67 85.41,34.4 85.41,33.83 85.31,33.72 84.06,33.72 81.18,30.84 80.25,30.84 79.97,30.56 79.97,30.29 79.87,30.19 79.46,30.19 79.36,30.29 79.36,30.56 79.09,30.84 77.91,30.84 77.91,30.85 77.87,30.85 77.66,31.05 76.94,31.05 76.63,31.37 v1(74.46,31.37) ; v1(79.5,58.09) 79.11,57.7 79.11,55.95 79.41,55.66 80.8,55.66 80.92,55.54 80.92,55.38 80.8,55.26 79.41,55.26 79.11,54.97 79.11,54.55 79.41,54.26 80.8,54.26 80.92,54.14 80.92,53.97 80.8,53.85 79.41,53.85 79.11,53.56 79.11,53.06 76.88,50.83 76.88,50.25 76.76,50.13 76.38,50.13 76.09,49.84 76.09,49.43 76.39,49.13 76.79,49.13 76.92,49 76.92,48.77 76.82,48.66 75.15,48.66 74.86,48.37 74.86,47.96 75.15,47.67 77.14,47.67 77.26,47.54 77.26,47.37 77.15,47.26 75.15,47.26 74.86,46.97 74.86,46.56 75.15,46.27 76.76,46.27 76.88,46.15 76.88,44.48 77.38,43.98 77.64,43.98 v1(77.85,43.77)
DDR_CLKN: length 94.3
  TOP w0.102: v1(93.34,33.3) 93.85,33.3 U21.K7 ; U11.M1 79.83,59.15 79.89,59.1 79.89,58.26 79.91,58.24 79.91,57.62 v1(79.83,57.54) ; v1(73.79,31.31) 73.79,33.37 73.97,33.55 74.93,33.55 U20.K7 75.66,32.82 76.17,32.82 76.35,32.64 76.53,32.64 76.71,32.82 77.29,32.82 78.17,33.7 78.81,34.33 78.81,35.03 79.64,35.86 79.64,37.09 79.35,37.39 78.32,37.39 78.2,37.51 78.2,37.67 78.32,37.79 79.47,37.79 79.75,38.08 79.75,38.49 79.45,38.79 78.32,38.79 78.2,38.91 78.2,39.08 78.32,39.19 79.51,39.19 79.8,39.48 79.8,39.89 79.51,40.19 78.14,40.19 78.02,40.31 78.02,40.48 78.13,40.6 79.53,40.6 79.81,40.87 79.81,41.29 79.51,41.59 78.13,41.59 78.04,41.69 78.04,41.86 78.18,42 79.35,42 79.64,42.29 79.64,43.37 78.74,44.27 78.01,44.27 v1(77.85,44.43)
  BOTTOM w0.102: v1(79.83,57.54) 79.41,57.12 79.41,56.08 79.53,55.96 80.92,55.96 81.21,55.67 81.21,55.25 80.92,54.96 79.53,54.96 79.41,54.84 79.41,54.67 79.53,54.56 80.92,54.56 81.21,54.26 81.21,53.85 80.92,53.56 79.53,53.56 79.41,53.44 79.41,52.94 77.17,50.71 77.17,50.12 76.88,49.83 76.5,49.83 76.39,49.72 76.39,49.55 76.51,49.43 76.92,49.43 77.22,49.13 77.22,48.64 76.94,48.37 75.27,48.37 75.16,48.25 75.16,48.08 75.27,47.96 77.26,47.96 77.56,47.66 77.56,47.25 77.28,46.97 75.27,46.97 75.16,46.85 75.16,46.68 75.27,46.56 76.88,46.56 77.17,46.27 77.17,44.61 77.51,44.27 77.69,44.27 v1(77.85,44.43) ; R508.2 99.82,33.21 99.54,33.49 95.84,33.49 95.66,33.3 v1(93.34,33.3) 93.22,33.41 92.39,33.41 92.3,33.32 91.72,33.32 91.67,33.37 91.42,33.37 91.36,33.42 91.34,33.42 91.33,33.43 86.59,33.43 86.32,33.7 86.32,34.25 86.19,34.38 85.81,34.38 85.71,34.27 85.71,33.7 85.43,33.43 84.18,33.43 81.3,30.54 80.37,30.54 80.27,30.44 80.27,30.17 79.99,29.9 79.34,29.9 79.07,30.17 79.07,30.44 78.97,30.54 77.76,30.54 77.54,30.76 76.82,30.76 76.51,31.07 74.74,31.07 74.53,30.86 73.95,30.86 73.79,31.02 v1(73.79,31.31)
DDR_CS0N: length 94.8
  TOP w0.102: U20.L2 71.26,32.37 v1(70.89,32) 70.34,32 70.18,32.16 68.89,32.16 68.15,32.91 68.15,37.74 67.69,38.2 67.69,39.32 67.82,39.45 67.82,41.15 v1(67.1,41.87) ; U11.M5 v1(79.36,62.52) ; U21.L2 v1(89.53,32.82)
  L3_SIG1 w0.102: v1(79.36,62.52) 79.88,62 79.88,60.68 77.31,58.1 77.31,57.75 77.42,57.63 77.8,57.63 77.92,57.51 77.92,57.35 77.8,57.23 77.42,57.23 77.31,57.11 77.31,56.94 77.42,56.82 77.8,56.82 77.92,56.7 77.92,56.53 77.8,56.41 77.42,56.41 77.31,56.29 77.31,55.64 77.09,55.42 76.92,55.42 76.66,55.69 76.49,55.69 76.37,55.57 76.37,55.4 76.63,55.14 76.63,54.97 76.52,54.85 76.35,54.85 76.08,55.11 75.92,55.11 75.8,54.99 75.8,54.83 76.06,54.56 76.06,54.39 75.94,54.27 75.77,54.27 75.51,54.54 75.34,54.54 75.22,54.42 75.22,54.25 75.48,53.99 75.48,53.82 75.37,53.7 75.2,53.7 74.93,53.96 74.77,53.96 74.65,53.84 74.65,53.68 74.91,53.41 74.91,53.24 74.79,53.12 74.62,53.12 74.36,53.39 74.19,53.39 74.07,53.27 74.07,53.1 74.33,52.84 74.33,52.67 74.22,52.55 74.05,52.55 73.78,52.81 73.62,52.81 73.5,52.69 73.5,52.52 73.76,52.26 73.76,52.09 73.64,51.97 73.47,51.97 73.21,52.24 73.04,52.24 72.92,52.12 72.92,51.95 73.18,51.69 73.18,51.52 73.07,51.4 72.9,51.4 72.63,51.66 72.47,51.66 72.35,51.54 72.35,51.37 72.61,51.11 72.61,50.94 70.43,48.77 70.43,48.54 70.33,48.43 70.33,48.27 70.63,47.96 70.63,47.79 70.51,47.67 70.35,47.67 70.04,47.98 69.87,47.98 69.75,47.86 69.75,47.69 70.06,47.39 70.06,47.22 69.94,47.1 69.77,47.1 69.47,47.4 69.3,47.4 69.18,47.28 69.18,47.11 69.48,46.81 69.48,46.64 69.36,46.52 69.2,46.52 68.89,46.83 68.72,46.83 68.66,46.77 68.66,46.6 69.95,45.31 69.95,45.14 69.83,45.02 69.67,45.02 68.38,46.31 68.21,46.31 68.09,46.19 68.09,46.02 69.07,45.04 69.07,44.87 68.95,44.75 68.79,44.75 67.8,45.74 67.63,45.74 66.95,45.05 66.95,44.22 67.1,44.07 v1(67.1,41.87)
  L4_SIG2 w0.102: v1(70.89,32) 71.32,32.42 71.83,32.42 71.95,32.3 72.31,32.3 72.36,32.26 74.89,32.26 75.37,32.74 75.53,32.74 75.53,32.74 78.2,32.74 78.35,32.89 79.85,32.89 81.3,34.34 83.71,34.34 83.83,34.22 83.83,34.1 83.95,33.98 84.12,33.98 84.24,34.1 84.24,34.57 84.34,34.68 84.51,34.68 84.64,34.55 84.64,34.1 84.76,33.98 84.93,33.98 85.05,34.1 85.05,34.57 85.16,34.68 85.33,34.68 85.45,34.55 85.45,34.1 85.57,33.98 85.74,33.98 85.86,34.1 85.86,34.22 85.98,34.34 86.28,34.34 87.34,33.28 87.58,33.04 87.58,32.59 87.81,32.36 88.87,32.36 89.36,31.88 90.91,31.88 91.03,32 91.03,32.26 90.91,32.38 89.96,32.38 v1(89.53,32.82)
  BOTTOM w0.102: v1(89.53,32.82) 89.31,32.6 88.13,32.6 87,31.46 87,29.52 86.2,28.73 86.2,28.42 R521.2
DDR_D0: length 37.7
  TOP w0.102: v1(68.12,38.46) 68.94,37.64 71.64,37.64 U20.E3 ; U11.E3 v1(74.88,61.17)
  BOTTOM w0.102: v1(68.12,38.46) 67.5,38.46 66.09,39.87 66.09,40.82 65.79,41.12 65.79,42.15 65.78,42.15 65.78,42.21 65,43 64.93,43 64.93,43 64.71,43 63.47,44.24 63.47,52.33 66.52,55.38 66.52,57.48 69.49,60.45 74.16,60.45 v1(74.88,61.17)
DDR_D1: length 37.8
  TOP w0.102: v1(73.44,37.52) 73.44,37.02 73.6,36.86 74.09,36.86 74.56,36.39 74.95,36.39 74.98,36.42 U20.F7 ; v1(73.48,57.3) 73.86,57.3 74.94,58.38 74.94,59.66 U11.E2
  BOTTOM w0.102: v1(73.44,37.52) 73.13,37.52 72.83,37.82 72.83,38.2 72.2,38.83 72.2,39.07 72.29,39.15 72.57,39.15 72.69,39.27 72.69,39.44 72.57,39.56 72.15,39.56 72.03,39.68 72.03,41.98 71.36,42.65 69.78,42.65 68.79,43.65 68.79,44.65 68.12,45.32 68.12,53.39 68,53.51 66.96,53.51 66.86,53.61 66.86,53.8 66.98,53.92 68,53.92 68.12,54.04 68.12,54.29 68.37,54.53 68.53,54.53 68.65,54.65 68.65,55.17 68.76,55.28 68.93,55.28 69.06,55.15 69.06,54.65 69.18,54.53 71.6,54.53 73.48,56.41 v1(73.48,57.3)
DDR_D2: length 37.7
  TOP w0.102: U20.F2 71.31,36.42 v1(71.7,36.81) ; v1(65.38,50.22) 65.38,51 65.47,51.09 65.72,51.09 65.81,51.18 65.81,51.31 65.72,51.4 65.47,51.4 65.38,51.48 65.38,51.77 68.18,54.57 70.06,54.57 71.9,56.4 73.41,56.4 75.29,58.28 U11.E1
  BOTTOM w0.102: v1(71.7,36.81) 71.7,37.93 69.89,39.75 68.2,39.75 67.69,40.26 67.69,41.95 65.82,43.81 65.05,43.81 64.6,44.26 64.6,45.24 64.72,45.35 65.06,45.35 65.18,45.47 65.18,45.64 65.06,45.76 64.72,45.76 64.6,45.88 64.6,46.05 64.72,46.17 65.06,46.17 65.18,46.29 65.18,46.45 65.06,46.57 64.72,46.57 64.6,46.69 64.6,46.86 64.72,46.98 65.06,46.98 65.18,47.1 65.18,47.27 65.06,47.39 64.72,47.39 64.6,47.51 64.6,47.71 64.87,47.98 65.28,48.38 65.5,48.6 65.5,48.74 65.99,49.23 65.99,49.61 v1(65.38,50.22)
DDR_D3: length 37.8
  TOP w0.102: U20.F8 75.72,36.08 74.36,36.08 73.79,36.64 73.47,36.64 72.52,37.59 72.02,37.59 71.73,37.88 71.73,38.03 71.4,38.36 71.23,38.36 70.8,38.79 70.8,38.96 70.6,39.16 70.43,39.16 69.29,40.3 69.29,41.96 67.64,43.62 v1(67.64,44.7) ; v1(74.8,60.48) 74.94,60.34 75.63,60.34 U11.F3
  BOTTOM w0.102: v1(67.64,44.7) 67.64,45.75 67.71,45.83 67.71,51.95 66.46,53.2 66.46,54.89 67.08,55.51 67.08,57.43 69.81,60.16 74.49,60.16 v1(74.8,60.48)
DDR_D4: length 37.7
  TOP w0.102: v1(73.26,35.34) 72.74,34.82 U20.H3 ; U11.G4 76.37,61.63 v1(76.08,62.08)
  BOTTOM w0.102: v1(73.26,35.34) 73.75,35.83 74.1,35.83 74.32,36.05 74.32,38.28 73.36,39.24 73.36,40.81 73.48,40.93 73.7,40.93 73.81,41.05 73.81,41.22 73.7,41.34 73.48,41.34 73.36,41.45 73.36,41.62 73.48,41.74 73.7,41.74 73.81,41.86 73.81,42.03 73.7,42.15 73.48,42.15 73.36,42.27 73.36,42.66 71.95,44.08 70.46,44.08 70.21,44.33 70.21,45.37 69.55,46.03 69.55,52.58 70.54,53.57 72.1,53.57 72.88,54.36 73.31,54.36 75.42,56.46 75.42,59.63 76.15,60.37 76.15,62 v1(76.08,62.08)
DDR_D5: length 37.8
  TOP w0.102: v1(73.62,36.23) 73.62,35.56 73.67,35.51 73.67,35.04 74.31,34.4 75.32,34.4 75.74,34.82 75.91,34.82 75.91,34.82 U20.H8 ; U11.G3 76.29,60.94 75.88,60.94 75.73,61.09 v1(75.49,61.09)
  BOTTOM w0.102: v1(75.49,61.09) 75.49,60.57 74.45,59.52 74.45,56.91 71.74,54.2 69.51,54.2 68.53,53.22 68.53,45.57 68.56,45.54 69.19,44.91 69.19,44.51 69.19,43.82 69.95,43.06 70.88,43.06 71.53,43.06 72.24,42.35 72.24,41.07 72.92,40.39 72.92,38.41 73.41,37.93 73.61,37.93 73.91,37.63 73.91,36.52 v1(73.62,36.23)
DDR_D6: length 37.7
  TOP w0.102: U20.G2 70.89,35.98 v1(70.87,35.98) ; U11.G2 76.28,59.69 76.28,57.51 73.87,55.1 72.76,55.1 70.89,53.23 70.52,53.23 67.37,50.07 67.24,50.07 67.04,50.27 66.92,50.27 66.83,50.18 66.83,50.05 67.03,49.85 67.03,49.73 66.67,49.38 v1(65.49,49.38)
  BOTTOM w0.102: v1(70.87,35.98) 71.29,36.41 71.29,37.9 70.07,39.11 70.07,39.13 69.73,39.47 67.21,39.47 66.5,40.18 66.5,40.99 66.19,41.29 66.19,42.38 65.17,43.41 64.88,43.41 63.88,44.41 63.88,49.03 64.23,49.38 v1(65.49,49.38)
DDR_D7: length 37.7
  TOP w0.102: v1(68.09,44.11) 68.09,45.01 67.83,45.28 66.95,45.28 65.97,46.26 65.97,48.04 70.75,52.82 71.06,52.82 72.86,54.63 74.06,54.63 76.59,57.15 U11.G1 ; v1(74.08,35.33) 74.08,35.04 74.42,34.7 75.14,34.7 U20.H7
  BOTTOM w0.102: v1(68.09,44.11) 68.09,43.77 69.5,42.36 71.35,42.36 71.78,41.93 71.78,38.96 72.63,38.11 72.63,37.61 73.22,37.02 73.22,35.87 72.86,35.51 72.86,35.07 73.1,34.83 73.93,34.83 74.08,34.98 v1(74.08,35.33)
DDR_D8: length 31.6
  TOP w0.102: v1(71.87,44.88) 71.87,43.53 73.63,41.77 73.63,39.49 72.52,38.38 72.52,38.23 72.62,38.13 72.82,38.13 73.68,38.99 73.9,38.99 74.87,38.02 U20.D7 ; v1(71.77,45.82) 72.12,46.18 73.18,46.18 73.61,46.6 73.61,47.12 73.38,47.35 73.38,50.07 72.75,50.7 71.86,50.7 71.74,50.82 71.74,51.04 71.85,51.15 73.18,51.15 73.3,51.27 73.3,52.4 76.98,56.09 76.98,56.25 77.24,56.51 U11.H1
  BOTTOM w0.102: v1(71.77,45.82) 71.77,45.62 71.87,45.52 v1(71.87,44.88)
DDR_D9: length 31.7
  TOP w0.102: v1(77.09,62.03) 77.34,62.03 77.36,62.05 77.56,62.05 77.89,62.38 U11.J6 ; U20.C3 72.88,39.64 72.88,41.04 70.07,43.85 70.07,44.08 70.19,44.19 70.32,44.19 70.43,44.31 70.43,44.48 70.32,44.6 70.19,44.6 70.07,44.72 70.07,45.17 70.19,45.29 70.52,45.29 70.64,45.41 70.64,45.58 70.52,45.7 70.19,45.7 70.07,45.82 70.07,46.16 v1(70.23,46.32)
  BOTTOM w0.102: v1(77.09,62.03) 76.74,62.03 76.4,61.69 76.4,60.27 75.69,59.56 75.69,56.45 72.31,53.07 70.75,53.07 70.08,52.39 70.08,47.57 70.64,47.01 70.64,46.72 v1(70.23,46.32)
DDR_D10: length 31.7
  TOP w0.102: v1(72.58,45.57) 72.58,44.83 72.28,44.53 72.28,43.86 72.82,43.32 72.99,43.32 73.32,43.66 73.49,43.66 73.61,43.54 73.61,43.37 73.27,43.03 73.27,42.86 74.05,42.09 74.05,39.29 74.93,38.41 75.93,38.41 76.06,38.54 U20.C8 ; U11.J5 77.83,61.95 v1(77.53,61.65)
  BOTTOM w0.102: v1(72.58,45.57) 72.58,45.64 71.5,46.72 71.5,47.04 71.38,47.17 71.05,47.17 70.71,47.51 70.71,50.53 72.27,52.1 72.27,52.3 76.07,56.1 76.07,59.33 76.6,59.86 76.6,61.26 76.97,61.63 77.51,61.63 v1(77.53,61.65)
DDR_D11: length 31.7
  TOP w0.102: v1(71.15,48.49) 71.15,49.14 70.47,49.81 69.24,49.81 68.58,49.15 68.58,48.71 68.78,48.51 68.78,48.3 68.58,48.11 68.58,46.46 69.26,45.78 69.26,43.39 71.64,41.01 71.64,39.2 U20.C2 ; v1(77.02,61.09) 77.09,61.09 77.23,61.23 77.81,61.23 U11.J4
  BOTTOM w0.102: v1(71.15,48.49) 71.15,50.34 74.23,53.43 74.23,53.69 76.45,55.91 76.45,59.03 76.91,59.49 76.91,60.97 v1(77.02,61.09)
DDR_D12: length 31.7
  TOP w0.102: v1(77.32,60.6) 77.37,60.6 77.41,60.65 U11.J3 ; v1(74.25,44.88) 74.25,45.07 74.5,45.31 74.78,45.31 75.51,44.58 75.51,43.5 75.39,43.38 75.39,42.83 75.25,42.69 75.08,42.69 74.46,43.32 74.29,43.32 74.17,43.2 74.17,43.03 74.57,42.64 74.57,40.69 74.69,40.57 74.81,40.57 74.94,40.69 74.94,41.51 75.03,41.6 75.55,41.6 75.64,41.51 75.64,40.54 75.52,40.42 U20.A7
  BOTTOM w0.102: v1(77.32,60.6) 77.32,60.04 77.32,59.36 76.83,58.88 76.83,55.78 76.32,55.26 76.32,54.88 71.7,50.27 71.7,47.99 72.1,47.6 73.13,47.6 73.58,47.15 73.58,45.55 v1(74.25,44.88)
DDR_D13: length 31.7
  TOP w0.102: v1(72.18,49.5) 71.37,49.5 70.24,50.63 69.31,50.63 68.17,49.5 68.17,46.02 68.85,45.34 68.85,43.16 70.62,41.39 70.63,41.39 70.87,41.15 70.87,41.15 71.26,40.75 U20.A2 ; v1(79.01,62.07) 79,62.07 78.54,62.53 U11.K6
  BOTTOM w0.102: v1(72.18,49.5) 72.18,50.13 76.71,54.66 76.71,54.97 77.17,55.42 77.17,58.78 77.76,59.37 77.76,61.23 78.6,62.06 79.01,62.06 v1(79.01,62.07)
DDR_D14: length 31.6
  TOP w0.102: U20.B8 76.47,40.03 77.06,40.03 77.34,40.31 77.34,41.33 76.4,42.27 76.15,42.27 75.79,42.62 75.79,43.21 75.91,43.33 75.91,43.77 77.15,45 77.15,48.91 77.03,49.03 76.51,49.03 76.39,49.15 76.39,49.32 76.51,49.44 77.03,49.44 77.15,49.56 77.15,49.72 77.03,49.84 76.51,49.84 76.39,49.96 76.39,50.13 76.51,50.25 77.03,50.25 77.15,50.37 77.15,50.54 77.03,50.66 76.51,50.66 76.39,50.78 76.39,50.94 76.51,51.06 77.03,51.06 77.15,51.18 77.15,51.35 77.03,51.47 76.51,51.47 76.39,51.59 76.39,51.76 76.51,51.88 77.03,51.88 77.15,52 77.15,53.36 v1(77.04,53.47) ; U11.K5 78.83,61.66 79.18,61.66 79.19,61.65 v1(79.41,61.65)
  BOTTOM w0.102: v1(77.04,53.47) 77.04,54.51 77.44,54.91 77.44,58.57 78.08,59.21 78.08,61.09 78.65,61.66 79.18,61.66 79.19,61.65 v1(79.41,61.65)
DDR_D15: length 31.7
  TOP w0.102: U11.K4 v1(79.01,61.25) ; U20.A3 72.06,41.22 69.67,43.62 69.67,45.99 69.32,46.34 69.32,46.61 69.59,46.88 70.52,46.88 70.64,46.99 70.64,47.28 70.52,47.4 69.34,47.4 69.15,47.59 69.15,47.82 69.34,48.02 69.62,48.02 69.74,48.14 69.74,48.48 69.86,48.6 70.03,48.6 70.15,48.48 70.15,48.14 70.27,48.02 71.51,48.02 72.11,48.61 v1(72.18,48.61)
  BOTTOM w0.102: v1(72.18,48.61) 73.08,48.61 77.87,53.4 77.87,58.59 78.48,59.2 78.48,60.72 v1(79.01,61.25)
DDR_D16: length 36.9
  TOP w0.102: U21.E3 90.34,36.83 88.47,36.83 87.94,37.36 87.3,37.36 87.03,37.63 v1(87.03,38.14) ; v1(83.31,61.66) U11.V5
  BOTTOM w0.102: v1(83.31,61.66) 83.72,61.25 83.72,58.8 83.03,58.12 83.03,54.57 87.05,50.56 87.05,50.27 86.93,50.15 86.36,50.15 86.24,50.03 86.24,49.86 86.36,49.74 86.93,49.74 87.05,49.63 87.05,49.46 86.93,49.34 86.36,49.34 86.24,49.22 86.24,49.05 86.36,48.93 86.93,48.93 87.05,48.81 87.05,48.44 87.26,48.23 87.26,44.39 87.96,43.69 87.96,43.35 87.96,43.35 87.96,42.46 87.96,41.54 87.03,40.61 87.03,40.29 86.91,40.17 86.36,40.17 86.24,40.05 86.24,39.88 86.36,39.76 86.91,39.76 87.03,39.64 87.03,39.47 86.91,39.36 86.36,39.36 86.24,39.24 86.24,39.07 86.36,38.95 86.91,38.95 87.03,38.83 v1(87.03,38.14)
DDR_D17: length 36.9
  TOP w0.102: U21.F7 92.95,36.42 v1(91.95,35.42) ; U11.V4 v1(83.31,60.85)
  BOTTOM w0.102: v1(91.95,35.42) 90.14,35.42 89.8,35.75 89.05,35.75 88.79,36 86.71,36 86.01,36.7 86.01,40.33 86.74,41.07 86.91,41.07 87.55,41.7 87.55,41.87 87.55,41.88 87.55,41.96 87.55,43.52 86.85,44.22 86.85,47.83 85.84,48.85 85.84,50.93 85.28,51.48 85.28,51.7 85.1,51.88 84.88,51.88 84.7,52.06 84.7,52.28 84.53,52.46 84.31,52.46 82.68,54.09 82.68,58.19 83.32,58.84 83.32,60.61 83.31,60.62 v1(83.31,60.85)
DDR_D18: length 36.9
  TOP w0.102: U21.F2 89.52,36.01 88.32,36.01 87.86,36.48 v1(87.86,36.83) ; U11.V3 v1(84.18,60.87)
  BOTTOM w0.102: v1(84.18,60.87) 84.18,58.83 83.39,58.04 83.39,55.06 87.52,50.93 87.52,48.76 87.67,48.61 87.67,47.37 87.79,47.25 87.89,47.25 88.01,47.13 88.01,46.96 87.89,46.84 87.79,46.84 87.67,46.72 87.67,44.56 88.76,43.46 88.76,41.08 89.12,40.72 89.12,39.04 89.36,38.81 89.36,38.15 89.03,37.82 88.34,37.82 88.18,37.98 88.18,38.92 88,39.11 87.77,39.11 87.57,38.91 87.57,37.61 87.48,37.52 86.34,37.52 86.25,37.43 86.25,37.3 86.34,37.21 87.48,37.21 v1(87.86,36.83)
DDR_D19: length 36.9
  TOP w0.102: U11.V2 84.18,60.45 84.6,60.45 v1(84.62,60.43) ; U21.F8 94.73,36.06 94.63,35.96 94.44,35.96 94.3,36.11 94.3,36.66 94.13,36.83 93.15,36.83 93.14,36.82 v1(93.11,36.82)
  BOTTOM w0.102: v1(84.62,60.43) 84.62,58.81 83.72,57.91 83.72,55.59 88.46,50.85 88.46,50.73 90.85,48.34 92.09,48.34 92.25,48.18 92.25,45.89 92.1,45.73 92.1,42.14 92,42.04 92,41.75 91.88,41.63 91.82,41.63 91.7,41.51 91.7,41.34 91.82,41.22 91.88,41.22 92,41.1 92,39.22 91.88,39.1 91.03,39.1 90.91,38.98 90.91,38.81 91.03,38.69 91.88,38.69 92,38.57 92,38.4 91.88,38.28 91.03,38.28 90.91,38.17 90.91,38 91.03,37.88 91.88,37.88 92,37.76 92,37.54 92.72,36.82 v1(93.11,36.82)
DDR_D20: length 36.9
  TOP w0.102: U11.V1 83.43,59.66 83.43,60.19 83.16,60.46 v1(82.9,60.46) ; U21.H3 v1(91.37,34.82)
  BOTTOM w0.102: v1(91.37,34.82) 91.3,34.75 87.03,34.75 85.45,36.34 85.45,40.42 86.49,41.47 86.74,41.47 87.15,41.87 87.15,42.12 87.15,42.13 87.15,42.55 87.15,43.32 86.45,44.02 86.45,47.66 85.43,48.68 85.43,50.72 84.99,51.15 84.66,51.15 84.54,51.28 84.54,51.6 84.42,51.73 84.09,51.73 83.96,51.85 83.96,52.18 83.84,52.3 83.51,52.3 83.39,52.43 83.39,52.75 83.27,52.88 82.94,52.88 82.81,53 82.81,53.33 82.22,53.92 82.22,58.5 82.19,58.53 82.19,58.87 82.9,59.58 v1(82.9,60.46)
DDR_D21: length 36.9
  TOP w0.102: U11.W4 84.49,61.3 84.8,60.99 85.38,60.99 v1(85.47,61.07) ; v1(94.29,34.43) U21.H8
  BOTTOM w0.102: v1(85.47,61.07) 85.7,60.84 85.7,60.56 85.95,60.31 85.95,58.57 86.77,57.76 86.77,54.85 89.94,51.68 89.94,51.27 91.29,49.91 92.86,49.91 94.31,48.46 94.31,48.06 94.43,47.94 94.65,47.94 94.77,47.82 94.77,47.65 94.65,47.53 94.43,47.53 94.31,47.41 94.31,47.24 94.43,47.12 94.65,47.12 94.77,47 94.77,46.84 94.65,46.72 94.43,46.72 94.31,46.6 94.31,45.81 95,45.13 95,42.94 93.42,41.37 93.42,37.59 93.9,37.11 93.9,35.61 93.46,35.17 93.23,35.17 93.09,35.03 93.09,34.83 93.28,34.64 94.08,34.64 v1(94.29,34.43)
DDR_D22: length 36.9
  TOP w0.102: U21.G2 90.3,35.99 v1(90.32,35.99) ; v1(84.79,61.72) U11.W5
  BOTTOM w0.102: v1(84.79,61.72) 85.02,61.49 85.02,60.91 85.38,60.55 85.38,58.59 86.41,57.56 86.41,54.5 89.48,51.43 89.48,51.15 91.12,49.5 92.49,49.5 93.31,48.69 93.31,48.42 93.43,48.3 93.72,48.3 93.84,48.18 93.84,48.02 93.72,47.9 93.43,47.9 93.31,47.78 93.31,47.61 93.43,47.49 93.72,47.49 93.84,47.37 93.84,47.2 93.72,47.08 93.43,47.08 93.31,46.96 93.31,46.24 94.57,44.98 94.57,43.17 93.01,41.62 93.01,38.05 93.14,37.92 93.14,37.56 93.55,37.16 93.55,36.55 92.99,35.99 v1(90.32,35.99)
DDR_D23: length 36.9
  TOP w0.102: v1(94.31,35.19) U21.H7 ; v1(85.46,62.17) 85.42,62.17 85.42,62.17 84.82,62.17 U11.W6
  BOTTOM w0.102: v1(94.31,35.19) 94.31,37.06 93.74,37.63 93.74,40.89 93.83,40.98 93.83,41.2 95.45,42.83 95.45,45 95.57,45.12 95.8,45.12 95.92,45.23 95.92,45.4 95.8,45.52 95.57,45.52 95.45,45.64 95.45,45.81 95.57,45.93 95.8,45.93 95.92,46.05 95.92,46.22 95.8,46.33 95.57,46.33 95.45,46.45 95.45,46.62 95.57,46.74 95.8,46.74 95.92,46.86 95.92,47.03 95.8,47.15 95.57,47.15 95.45,47.27 95.45,48.2 93.33,50.32 91.46,50.32 90.39,51.39 90.39,51.9 87.15,55.14 87.15,57.96 86.44,58.67 86.44,60.12 85.95,60.6 85.95,61.26 85.46,61.75 v1(85.46,62.17)
DDR_D24: length 36.7
  TOP w0.102: v1(88.53,46.41) 88.53,46.55 88.12,46.96 88.12,47.88 89.02,48.78 89.02,50.07 88.5,50.59 88.24,50.59 85.39,53.44 83.98,54.85 83.98,56.39 83.86,56.51 83.86,57.56 84.73,58.43 84.73,59.69 U11.Y2 ; U21.D7 93.69,37.78 92.59,37.78 92.19,37.38 91.05,37.38 90.75,37.68 88.13,37.68 87.92,37.88 87.92,39.13 87.83,39.21 87.41,39.21 87.32,39.3 87.32,39.43 87.41,39.52 87.83,39.52 87.92,39.61 87.92,39.73 87.83,39.82 87.41,39.82 87.32,39.91 87.32,40.04 87.41,40.13 87.83,40.13 87.92,40.22 87.92,40.52 88.42,41.03 88.42,41.21 88.3,41.33 88.08,41.33 87.96,41.45 87.96,41.62 88.08,41.73 88.3,41.73 88.42,41.85 88.42,42.02 88.3,42.14 88.08,42.14 87.96,42.26 87.96,42.43 88.08,42.55 88.3,42.55 88.42,42.67 88.42,42.83 88.3,42.95 88.08,42.95 87.96,43.07 87.96,43.24 88.08,43.36 88.3,43.36 88.42,43.48 88.42,43.65 88.3,43.77 88.08,43.77 87.96,43.89 87.96,44.05 88.08,44.17 88.3,44.17 88.42,44.29 v1(88.42,44.77)
  BOTTOM w0.102: v1(88.53,46.41) 88.53,46.28 88.42,46.18 v1(88.42,44.77)
DDR_D25: length 36.6
  TOP w0.102: U21.C3 91.49,38.82 91.98,39.31 91.98,40.82 91.86,40.94 91.53,40.94 91.41,41.05 91.41,41.22 91.53,41.34 91.86,41.34 91.98,41.46 91.98,42.17 92.15,42.34 92.52,42.34 92.65,42.47 92.65,42.78 92.52,42.91 91.92,42.91 91.8,43.02 91.8,43.28 91.92,43.4 92.6,43.4 92.71,43.51 92.71,43.67 92.57,43.81 91.92,43.81 91.8,43.93 91.8,44.09 91.92,44.21 92.97,44.21 93.08,44.32 93.08,44.52 92.98,44.62 91.92,44.62 91.8,44.74 91.8,44.91 91.92,45.03 92.44,45.03 92.56,45.15 92.56,45.45 91.71,46.31 v1(91.52,46.31) ; U11.Y3 85.34,60.34 85.34,58.56 86.4,57.51 86.4,56.46 85.88,55.93 85.88,54.44 87.97,52.35 92.22,52.35 92.67,51.9 92.67,50.07 91.52,48.91 v1(91.52,47.54)
  BOTTOM w0.102: v1(91.52,46.31) 91.74,46.54 91.74,47.31 v1(91.52,47.54)
DDR_D26: length 36.8
  TOP w0.102: U11.Y4 85.29,61.56 85.74,61.56 v1(86.06,61.88) ; v1(94.07,52.87) 94.07,52.66 94.2,52.53 94.2,52.2 94.67,51.74 94.67,48.52 95.05,48.14 95.05,46.91 94.67,46.52 94.67,45.44 94.57,45.34 94.57,44.86 94.69,44.74 95.33,44.74 95.45,44.62 95.45,44.45 95.33,44.33 94.69,44.33 94.57,44.21 94.57,44.05 94.69,43.93 95.5,43.93 95.62,43.8 95.62,43.63 95.51,43.52 94.69,43.52 94.57,43.4 94.57,43.23 94.69,43.11 95.39,43.11 95.5,43.01 95.5,42.84 95.37,42.71 94.69,42.71 94.57,42.59 94.57,42.23 93.53,41.2 93.53,40.33 93.9,39.96 94.07,39.96 94.27,39.76 94.27,39.28 U21.C8
  BOTTOM w0.102: v1(86.06,61.88) 86.16,61.77 86.16,60.83 86.97,60.02 86.97,58.75 87.5,58.22 87.5,55.75 89.18,54.07 93.6,54.07 94.07,53.6 v1(94.07,52.87)
DDR_D27: length 36.8
  TOP w0.102: v1(86.6,60.96) 86.3,60.65 U11.AA3 ; v1(92.1,51.68) 92.19,51.59 92.19,50.23 90.99,49.03 90.99,45.82 91.12,45.7 91.58,45.7 91.7,45.57 91.7,45.4 91.59,45.29 91.12,45.29 90.99,45.16 90.99,44.86 91.11,44.74 91.27,44.74 91.39,44.62 91.39,44.45 91.27,44.33 91.11,44.33 90.99,44.21 90.99,44.04 91.11,43.92 91.27,43.92 91.39,43.81 91.39,43.64 91.27,43.52 91.11,43.52 90.99,43.4 90.99,43.23 91.11,43.11 91.27,43.11 91.39,42.99 91.39,42.82 91.27,42.71 91.11,42.71 90.99,42.59 90.99,42.42 91.11,42.3 91.46,42.3 91.58,42.18 91.58,42.01 91.46,41.89 91.11,41.89 90.99,41.77 90.99,40.79 91.59,40.19 91.59,39.7 91.05,39.16 90.27,39.16 U21.C2
  BOTTOM w0.102: v1(92.1,51.68) 94.04,51.68 94.52,52.16 94.52,53.77 93.77,54.53 89.37,54.53 87.88,56.01 87.88,58.47 87.48,58.87 87.48,60.09 v1(86.6,60.96)
DDR_D28: length 36.8
  TOP w0.102: U21.A7 94.02,40.51 94.02,41.07 95.06,42.11 95.71,42.11 v1(95.95,42.35) ; v1(96.14,43.95) 95.86,44.23 95.86,44.93 95.17,45.62 95.17,46.43 95.45,46.71 95.45,48.38 95.11,48.72 95.11,49.6 95.34,49.83 97.56,49.83 97.68,49.95 97.68,50.11 97.56,50.23 95.34,50.23 95.22,50.35 95.22,50.52 95.34,50.64 97.6,50.64 97.71,50.75 97.71,50.92 97.59,51.05 95.34,51.05 95.22,51.17 95.22,51.8 94.61,52.41 94.61,52.7 94.52,52.79 94.52,53.54 92.6,55.47 88.91,55.47 87.89,56.49 87.89,57.99 86.68,59.2 86.68,59.66 U11.AB2
  BOTTOM w0.102: v1(95.95,42.35) 95.95,42.6 95.96,42.61 95.96,43.77 v1(96.14,43.95)
DDR_D29: length 36.7
  TOP w0.102: U21.A2 90.12,40.6 90.12,41.02 90,41.14 89.87,41.14 89.75,41.26 89.75,41.43 89.87,41.55 90,41.55 90.12,41.67 90.12,41.83 90,41.95 89.87,41.95 89.75,42.07 89.75,42.24 89.87,42.36 90,42.36 90.12,42.48 90.12,42.65 90,42.77 89.87,42.77 89.75,42.89 89.75,43.05 89.87,43.17 90,43.17 90.12,43.29 90.12,43.46 90,43.58 89.87,43.58 89.75,43.7 89.75,43.87 89.87,43.99 90,43.99 90.12,44.11 90.12,45.47 90,45.59 89.15,45.59 89.03,45.71 89.03,45.88 89.15,45.99 90,45.99 90.12,46.11 90.12,49.48 90.98,50.34 90.98,50.57 90.87,50.68 90.23,50.68 90.12,50.8 90.12,50.96 90.23,51.07 91,51.07 91.11,51.19 v1(91.11,51.69) ; v1(93.59,53.41) 93.13,53.87 92.2,53.87 91.06,55.01 88.77,55.01 87.65,56.13 87.65,57.9 86.34,59.22 86.34,59.35 U11.AB1
  BOTTOM w0.102: v1(91.11,51.69) 91.11,52.24 91,52.36 90.71,52.36 90.6,52.47 90.6,52.64 90.71,52.75 91,52.75 91.11,52.86 91.11,53.47 91.23,53.6 91.6,53.6 91.72,53.48 91.72,52.44 91.83,52.32 91.99,52.32 92.11,52.44 92.11,53.28 92.22,53.39 92.39,53.39 92.5,53.28 92.5,52.44 92.62,52.32 92.78,52.32 92.89,52.44 92.89,53.14 93.17,53.41 v1(93.59,53.41)
